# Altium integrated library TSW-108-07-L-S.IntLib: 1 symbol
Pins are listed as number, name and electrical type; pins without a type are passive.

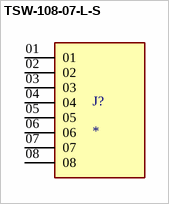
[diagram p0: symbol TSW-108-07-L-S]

## TSW-108-07-L-S
designator J?
MF: Samtec Inc.; MP: TSW-108-07-L-S
footprint SAMTEC_TSW-108-07-L-S
pins: 01, 02, 03, 04, 05, 06, 07, 08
